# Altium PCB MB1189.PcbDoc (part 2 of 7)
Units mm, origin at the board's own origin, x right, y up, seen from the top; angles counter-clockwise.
Board outline 60.03 x 127.03 mm, 6 copper layers (TOP, L2_GND, L3_VCC, L4_SIG, L5_GND, BOTTOM), stack 1.58 mm thick; 273 components, 264 nets, 1114 pads, 811 vias.
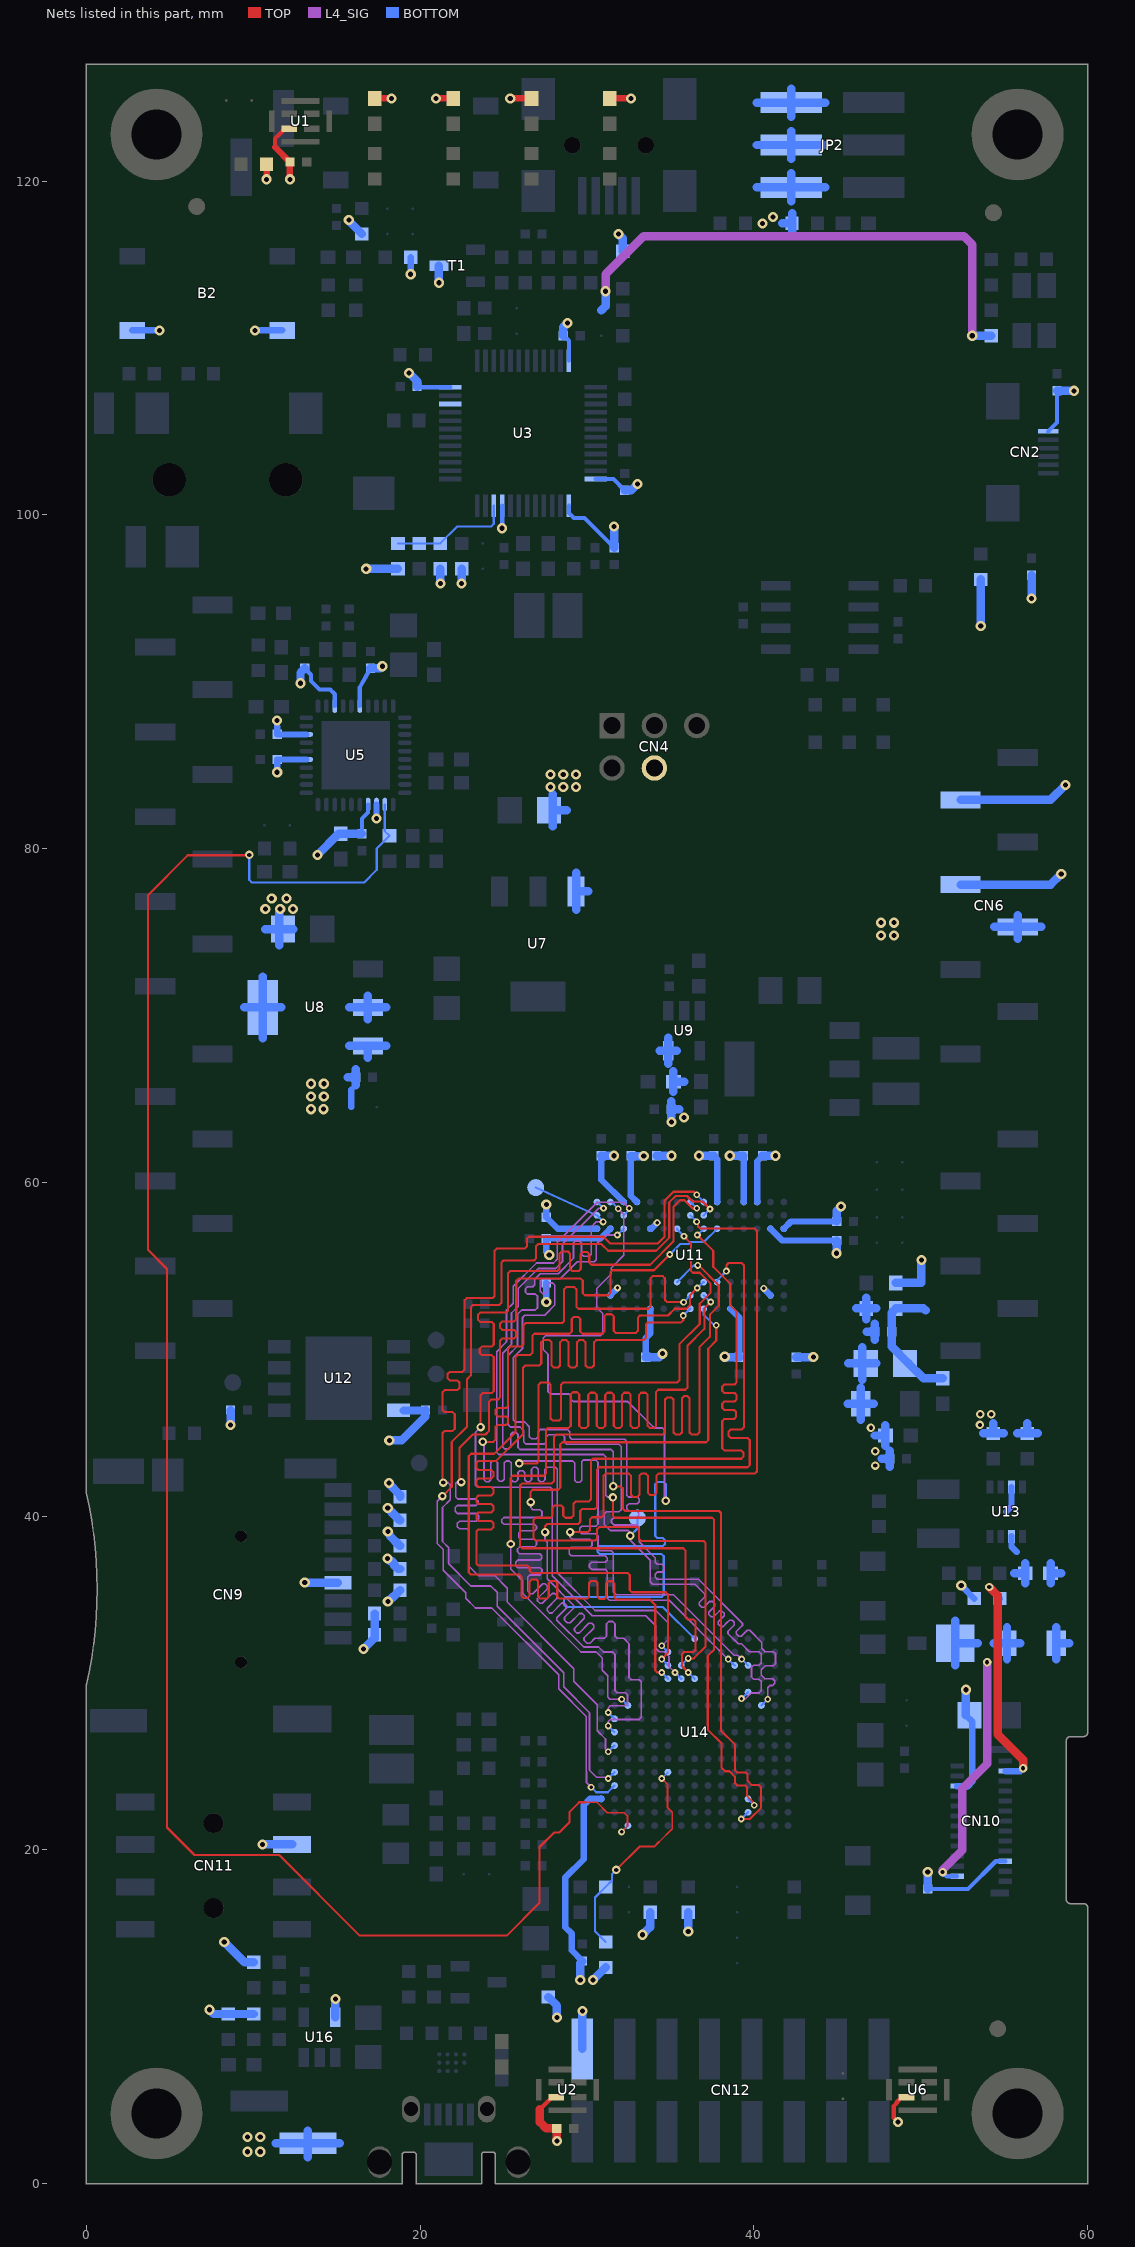
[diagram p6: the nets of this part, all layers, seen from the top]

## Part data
B1: library part "SW PUSHBUTTON", "Push-Button BLACK", Manuf_1="CHAU HUA"
B2: library part "SW PUSHBUTTON", "Push-Button BLUE", Manuf_1="CHAU HUA"
C1 C2 C41 C42 C43 C44 C45 C46 C47 C48 C49 C50 C51 C52 C55 C57 C58 C59 C62 C77 C78 C87: library part Cap, "Capacitor", Manuf_1=YAGEO, Manuf_Part_1=CC0402KRX7R7BB104
C3 C6 C16 C17 C23 C25 C30 C53 C54 C64 C67 C68 C69 C70 C71 C72 C73 C74 C75 C84 C88 C89 C90 C91 C92 C95 C97: library part CAP, "Capacitor", Manuf_1=YAGEO, Manuf_Part_1=CC0402KRX7R7BB104
C4: library part CAP, "Capacitor"
C5 C7 C8 C9 C12 C14 C34 C40: library part Capacitor_ST, "Capacitor 0402 / 0603 / 0805", Manuf_1=YAGEO, Manuf_Part_1=CC0402KRX7R7BB104
C10 C11: library part Capacitor_ST, "Capacitor 0402 / 0603 / 0805", Manuf_1=YAGEO, Manuf_Part_1=CC0603JRNPO9BN100
C13: library part Cap, "Capacitor"
C15 C29 C32 C35 C37 C56: library part Cap_TAJA106K016R, "Capacitor, Tantalum, 10uF, 16V, 10%, 3Ohms, pkg Type_A (3216 metric), T=1.6mm", Manuf_1=AVX, Manuf_Part_1=TAJA106K016R
C18 C19 C22 C31: library part CAP, "Capacitor", Manuf_1=YAGEO, Manuf_Part_1=CC0603KRX5R7BB105
C20 C21: library part Cap_22nF_X7R_10%_0603, "Capacitor,22nF,50V,X7R,10%,0603,YAGEO", Manuf_1=YAGEO, Manuf_Part_1=CC0603KRX7R9BB223
C24 C27: library part Cap_150pF_NPO_5%_0603, "Capacitor,150pF,50V,NPO,5%,0603,YAGEO", Manuf_1=YAGEO, Manuf_Part_1=CC0603JRNPO9BN151
C26: library part Cap_20pF_NPO_5%_0402, "Capacitor,20pF,50V,NPO,5%,0402,YAGEO", Manuf_1=YAGEO, Manuf_Part_1=CC0402JRNPO9BN200
C33 C38: library part "CAP SMD 0603  X5R 1µF 25V 10%", "Capacitor", Manuf_1=YAGEO, Manuf_Part_1=CC0603KRX5R7BB105, Rated voltage=25V, Temperature Max=+125°C, Temperature Min=-55°C, Tolerance=10%
C36: library part Cap_TAJB106K025RNJ, "Capacitor, Tantalum, 10uF, 25V, 10%, 2.5ohms, pkg Type_B (3528 metric), T=1.9mm", Manuf_1=AVX, Manuf_Part_1=TAJB106K025RNJ
C39: library part "CAP SMD 0603  X7R 10000PF 50V 10%", "0603  X7R 10NF", Manuf_1=YAGEO, Manuf_Part_1=CC0603KRX7R9BB103, Rated voltage=50V, Temperature Max=+125°C, Temperature Min=-55°C, Tolerance=10%
C60 C82 C98 C101: library part Cap_TAJA475K016R, "Capacitor, Tantalum, 4.7uF, 16V, 10%, 4ohms, pkg Type_A (3216 metric), T=1.6mm", Manuf_1=AVX, Manuf_Part_1=TAJA475K016R
C61: library part "Cap Pol1", "Polarized Capacitor (Radial)", Manuf_1=YAGEO, Manuf_Part_1=CC1206KKX7R8BB475
C63 C66: library part CAP, "Capacitor", Manuf_1=YAGEO, Manuf_Part_1=CC0603KRX7R9BB103
C65 C80 C86: library part Cap_TAJA105K016RNJ, "Capacitor, Tantalum, 1uF, 16V, 10%, 11Ohms, pkg Type_A (3216 metric), T=1.6mm", Manuf_1=AVX, Manuf_Part_1=TAJA105K016RNJ
C76 C81 C96: library part Cap, "Capacitor", Manuf_1=YAGEO, Manuf_Part_1=CC1206KKX7R7BB225
C79: library part CAP, "Capacitor", Manuf_1=YAGEO, Manuf_Part_1=CC1206KKX7R9BB475
C83 C85: library part CAP, "Capacitor", Manuf_1=YAGEO, Manuf_Part_1=CC0603CRNPO9BN8R2
C93 C94: library part CAP, "Capacitor", Manuf_1=YAGEO, Manuf_Part_1=CC0603CRNPO9BN3R0
CN1: library part "USB-MINI-typeB connector", "USB-MINI-typeB connector", Manuf_1=NELTRON, Manuf_Part_1=5075BMR-05-SM
CN2: "ZIF connector placed bottom side", Manuf_1=ATOM, Manuf_2=Hirose, Manuf_Part_1=FPC05006-09200
CN3: Manuf_1=QIAOD
CN4: library part "Header 3X2", "Header, 3-Pin, Dual row"
CN5: library part "Header 10X1_Female", "Header, 10-Pin, Single row,female", Manuf_1=SAMTEC, Manuf_Part_1=SSW-110-22-x-S-VS
CN6 CN7: library part "Header 8X1_Female", "Header, 8-Pin, Single row,female", Manuf_1=SAMTEC, Manuf_Part_1=SSW-108-22-x-S-VS
CN8: library part "Header 6X1_Female", "Header, 6-Pin, Single row,female SMD", Manuf_1=SAMTEC, Manuf_Part_1=SSW-106-22-x-S-VS
CN9: library part SMS016AFA5E, "MicroSD Card Conn, Reversed-Type, Mnt Push-Push, Positionning holes", Manuf_1=Yamaichi
CN10: "ZIF connector placed bottom side", Manuf_1=ATOM, Manuf_2=Hirose, Manuf_Part_1=FPC03025-14201
CN11: library part SSM-104-L-DH, "Header, 4-Pin, Dual row", Manuf_1=SAMTEC
CN12: library part "Header 8X2", "Header, 8-Pin, Dual row", Manuf_1=SAMTEC, Manuf_Part_1=TSM-108-01-x-DV
CN13: Manuf_1=MOLEX
D1 D2 D3 D4 U4: Manuf_1=ST
D5: "2-line IPAD, EMI filter including ESD protection", Manuf_1=ST
JP1 JP5: library part JP2, Manuf_1=SAMTEC, Manuf_Part_1=TSM-102-01-x-SV
JP2: library part "Header 3X2", "Header, 3-Pin, Dual row", Manuf_1=SAMTEC, Manuf_Part_1=TSM-103-01-x-DV
L1 L2 L3 L5: library part Inductor, "Inductor", Manuf_1="Tai-Tech Advanced Electronics", Manuf_Part_1=FCM1608KF-601T05
L4: library part Inductor, "Inductor", Manuf_1="Murata Manufacturing", Manuf_Part_1=LQH32PN4R7NN0L
LD1 LD7 LD8: library part LED2, "Typical RED, GREEN, YELLOW, AMBER GaAs LED", Manuf_1="Everlight Electronics", Manuf_Part_1=19-217/G7C-AN1P2/3T
LD2: library part LED2, "Typical RED, GREEN, YELLOW, AMBER GaAs LED", Manuf_1="Everlight Electronics", Manuf_Part_1=19-217/S2C-AM2N2VY/3T
LD3 LD5 LD9: library part LED2, "Typical RED, GREEN, YELLOW, AMBER GaAs LED", Manuf_1="Everlight Electronics", Manuf_Part_1=19-217/R6C-AL1M2VY/3T
LD4: library part LED2, "Typical RED, GREEN, YELLOW, AMBER GaAs LED", Manuf_1="Everlight Electronics", Manuf_Part_1=19-217/BHC-ZL1M2RY/3T
LD6: library part HSMF-A201-A00J1, Manuf_1=EVERLIGHT
R1: library part Res_0_5%_0402, "Resistor", Manuf_1=YAGEO, Manuf_Part_1=RC0603FR-0710KL
R2 R49: library part Res1, "Resistor", Manuf_1=YAGEO, Manuf_Part_1=RC0603FR-07510RL
R3 R4 R5 R158: library part Res1, "Resistor", Manuf_1=YAGEO, Manuf_Part_1=RC0603FR-07680RL
R6 R8: library part res1, "Resistor", Manuf_1=YAGEO, Manuf_Part_1=RC0603FR-07100KL
R7: library part res1, "Resistor", Manuf_1=YAGEO, Manuf_Part_1=RC0603FR-07820RL
R9 R122 R149 R152: library part Res1, "Resistor", Manuf_1=YAGEO, Manuf_Part_1=RC0402FR-0710KL
R10 R11 R17: library part Res1, "Resistor", Manuf_1=YAGEO, Manuf_Part_1=RC0603FR-07100RL
R12: library part Resistor_ST, "Resistor", Manuf_1=YAGEO, Manuf_Part_1=RC0603FR-071K5L
R13 R14: library part Resistor_ST, "Resistor", Manuf_1=YAGEO, Manuf_Part_1=RC0603JR-070RL
R15 R35: library part Resistor_ST, "Resistor 0402 / 0603 / 0805", Manuf_1=YAGEO, Manuf_Part_1=RC0603FR-07100RL
R16: library part Res1, "Resistor", Manuf_1=YAGEO, Manuf_Part_1=RC0603FR-0736KL
R18: library part Res1, "Resistor", Manuf_1=YAGEO, Manuf_Part_1=RC0603FR-07330RL
R19: library part res1, "Resistor", Manuf_1=YAGEO, Manuf_Part_1=RC0603FR-07220KL
R20: library part Resistor_ST, "Resistor", Manuf_1=YAGEO, Manuf_Part_1=RC0603FR-07100RL
R21 R23 R24 R41 R46 R57 R87 R117 R123 R131 R132 R133 R135 R151 R156 R159 R160 R161: library part Res1, "Resistor", Manuf_1=YAGEO, Manuf_Part_1=RC0603JR-070RL
R22: library part Res1, "Resistor", Manuf_1=YAGEO, Manuf_Part_1=RC0603FR-072K7L
R25 R36 R118: library part Res1, "Resistor", Manuf_1=YAGEO, Manuf_Part_1=RC0603FR-074K7L
R26 R27 R30: library part Resistor_ST, "Resistor 0402 / 0603 / 0805", Manuf_1=YAGEO, Manuf_Part_1=RC0603FR-07100KL
R28 R38: library part Resistor_ST, "Resistor", Manuf_1=YAGEO, Manuf_Part_1=RC0402FR-0710KL
R29 R31: library part Resistor_ST, "Resistor 0402 / 0603 / 0805"
R32 R33: library part Resistor_ST, "Resistor 0402 / 0603 / 0805", Manuf_1=YAGEO, Manuf_Part_1=RC0603FR-074K7L
R34: library part Res1, "Resistor", Manuf_1=YAGEO, Manuf_Part_1=RC0402FR-07100KL
R37: library part Resistor_ST, "Resistor 0402 / 0603 / 0805", Manuf_1=YAGEO, Manuf_Part_1=RC0603FR-072K7L
R39 R40: library part Res_51_1%_0402, "Resistor", Manuf_1=YAGEO, Manuf_Part_1=RC0402FR-0751RL
R42 R59: library part Res1, "Resistor", Manuf_1=YAGEO, Manuf_Part_1=RC0603FR-07100KL
R43 R119 R144: library part Res1, "Resistor"
R47 R48: library part Res1, "Resistor", Manuf_1=YAGEO, Manuf_Part_1=RC0603FR-0747KL
R55: library part Res_10K_1%_0402, "Resistor", Manuf_1=YAGEO, Manuf_Part_1=RC0402FR-0710KL
R58: library part Res1, "Resistor", Manuf_1=YAGEO, Manuf_Part_1=RC0603FR-0710RL
R86 R114 R115 R116 R120 R155 R157: library part res1, "Resistor", Manuf_1=YAGEO, Manuf_Part_1=RC0603FR-0747KL
R121 R124: library part Res1, "Resistor", Manuf_1=YAGEO, Manuf_Part_1=RC0603FR-072K2L
R140 R142: library part Res1, "Resistor", Manuf_1=YAGEO, Manuf_Part_1=RC0603FR-071K5L
R143: library part res1, "Resistor", Manuf_1=YAGEO, Manuf_Part_1=RC0603FR-07510RL
R150: library part res1, "Resistor"
R153: library part res1, "Resistor", Manuf_1=YAGEO, Manuf_Part_1=RC0603FR-07330RL
R154: library part res1, "Resistor", Manuf_1=YAGEO, Manuf_Part_1=RC0603FR-0710KL
SB1 SB2 SB3 SB4 SB5 SB6 SB7 SB8 SB9 SB10 SB11 SB12 SB13 SB14 SB15 SB16 SB17 SB18 SB19: library part "Circuit Breaker", "Circuit Breaker"
T1 T3: library part NPN, "NPN Bipolar Transistor", Manuf_Part_1=MMBT9013
U1 U2 U6: "MEMS audio sensor omnidirectional digital microphone for industrial applications", Manuf_1=ST
U3: library part STM32F10x(48pin), Manuf_1=ST, Manuf_Part_1=STM32F103CBT6
U5: "Low Power, Stereo DAC w/Headphone & Speaker Amps", Manuf_1=Cirrus, Manuf_Part_1=CS43L22-CNZ
U7: "LOW DROP FIXED AND ADJUSTABLE POSITIVE VOLTAGE REGULATORS (3.3 Volts)", Manuf_1=ST
U8 U10: library part LD1117, Manuf_1=ST
U9: "Ultra low drop-low noise BiCMOS voltage, regulators low ESR capacitors compatible", Manuf_1=ST
U11: library part IS42S32400F-6BL, "SDRAM 128MBit 166MHZ 90BGA", Manuf_1=ISSI
U12: library part MT25QL128ABA1EW9-0SIT, "128Mb, 3V, Multiple I/O Serial Flash Memory, Quad/Dual", Manuf_1=MICRON
U13: library part STLD40DPMR, Manuf_1=ST
U14: library part Manta_Dragon_TFBGA216, Manuf_1=ST, Manuf_Part_1="STM32F469NIH6U cut 1.0"
U16: library part STMPS2141STR, Manuf_1=ST
X1 X2: library part XTAL_8M_NX3225GD, "Crystal 8Mhz, 8pF, -+50PPM, SMD", Manuf_1=NDK, Manuf_Part_1="NX3225GD 8MHz EXS00A-CG04874", Manuf_Part_2=NX3225GD-8.000M-STD-CRA-3
X3: library part XTAL_32K_NX3215SA, "Crystal 32.768kHz, 6pF, -+20PPM, R=50K, SMD", Manuf_1=NDK, Manuf_Part_1="NX3215SA 32.768KHz EXS00A-MU00525"
Z1: library part "D Schottky", "Schottky Diode", Manuf_1=ST

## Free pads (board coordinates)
  round 0.508 on Mech16: 1(-26.171,-56.053) 1(115.945,-55.727)
  round 1.016 smd far side mask+1.016: ""(6.604,118.491) ""(54.356,118.11) ""(54.61,9.271)
  round 1.016 smd mask+1.016: ""(6.604,118.491) ""(54.356,118.11) ""(54.61,9.271)

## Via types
v1: diameter 0.61/0.61/0.61 (per signal layer), hole 0.305, TOP to BOTTOM, 321 vias
v2: diameter 0.508/0.508/0.508 (per signal layer), hole 0.254, TOP to BOTTOM, 247 vias
v3: diameter 0.406/0.406/0.406 (per signal layer), hole 0.203, TOP to BOTTOM, 243 vias

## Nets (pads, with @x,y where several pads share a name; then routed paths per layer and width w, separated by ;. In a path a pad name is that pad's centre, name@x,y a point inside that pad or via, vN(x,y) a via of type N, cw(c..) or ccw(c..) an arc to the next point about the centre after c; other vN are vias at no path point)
+1V8: C16.1 C17.1 C30.1 C31.1 C32.1 U5.13 U5.16 U5.34 U8.2 U8.4 | length 25.8
  BOTTOM w0.254: C17.1@13.081,90.805 13.462,90.424 13.462,90.043 13.97,89.535 14.605,89.535 14.879,89.261 U5.13@14.879,88.548 ; U5.16@16.379,88.548 16.379,89.658 C16.1@17.018,90.805 ; C30.1@16.51,80.899 16.51,81.8 16.879,82.169 U5.34@16.879,82.648
  BOTTOM w0.508: 9.46,70.485 U8.4@10.566,70.485 ; 10.566,68.63 U8.4@10.566,70.485 ; 10.566,72.34 U8.4@10.566,70.485 ; 10.718,75.184 C32.1@11.557,75.184 ; 11.557,74.218 C32.1@11.557,75.184 ; v1@11.557,76.15 C32.1@11.557,75.184 ; 11.671,70.485 U8.4@10.566,70.485 ; C32.1@12.396,75.184 C32.1@11.557,75.184 ; v1(12.827,89.916) 12.827,90.551 C17.1@13.081,90.805 ; v1(13.843,79.629) 15.113,80.899 C31.1@15.24,80.899 C30.1@16.51,80.899 ; 15.761,70.485 U8.2@16.866,70.485 ; 16.866,69.773 U8.2@16.866,70.485 ; 16.866,71.197 U8.2@16.866,70.485 ; C16.1@17.018,90.805 17.602,90.805 v1(17.729,90.932) ; 17.972,70.485 U8.2@16.866,70.485
  other v1: 10.719,76.378 11.608,76.378 12.37,76.378 11.1,77.013 11.989,77.013
+3V3: B2.1 B2.4 C1.2 C2.2 C6.2 C23.2 C25.1 C41.1 C42.1 C43.1 C44.1 C45.1 C46.1 C47.1 C48.1 C49.1 C50.1 C51.1 C52.1 C57.1 C58.1 C59.1 C62.1 C82.1 C97.2 CN2.1 CN6.2 CN6.4 CN9.4 CN10.6 CN10.21 CN11.5 CN12.1 JP5.1 LD1.1 LD2.1 LD3.1 LD4.1 R1.2 R6.1 R10.1 R33.1 R34.1 R36.1 R43.1 R55.2 R86.1 R114.1 R115.1 R116.1 R118.2 R120.1 R121.1 R124.1 R140.1 R142.1 R149.2 R150.2 R153.2 R157.1 R158.2 SB8.2 U1.1 U2.1 U5.5 U5.8 U5.33 U6.1 U8.3 U11.A7 U11.B2 U11.B7 U11.C9 U11.D9 U11.E1 U11.F9 U11.L1 U11.L7 U11.M9 U11.N9 U11.P2 U11.P7 U11.R7 U12.8 U14.C1 | length 166.9
  TOP w0.254: 11.303,122.047 11.303,122.554 11.554,122.805 ; 11.554,122.806 11.894,123.146 U1.1@12.152,123.146 ; 27.178,4.444 27.556,4.822 ; 27.556,4.823 27.896,5.163 U2.1@28.154,5.163 ; v1(48.641,3.683) 48.387,3.937 48.387,4.651 48.558,4.822 48.558,4.87 48.851,5.163 U6.1@49.156,5.163
  TOP w0.381: v1(10.795,120.117) R1.2@10.795,121.031 ; 11.303,122.047 C1.2@12.192,121.158 v1(12.192,120.117) ; LD1.1@17.272,124.968 v1(18.288,124.968) ; v1(20.955,124.968) LD2.1@21.971,124.968 ; v1(25.4,124.968) LD3.1@26.67,124.968 ; LD4.1@31.369,124.968 v1(32.639,124.968)
  TOP w0.508: 27.178,4.444 27.178,3.683 27.559,3.302 C2.2@28.194,3.302 v1(28.194,2.54)
  BOTTOM w0.254: C97.2@50.419,17.653 52.832,17.653 54.496,19.317 CN10.21@55.075,19.317 ; CN2.1@57.635,105.009 58.166,105.54 C6.2@58.166,107.442
  BOTTOM w0.381: B2.4@2.739,111.061 v1(4.381,111.061) ; v1(10.096,111.061) B2.1@11.739,111.061 ; v1(11.422,87.681) 11.422,87.325 11.43,87.317 C23.2@11.43,86.868 11.45,86.848 U5.8@13.179,86.848 ; v1(11.43,84.582) C25.1@11.43,85.344 11.815,85.348 U5.5@13.179,85.348 ; SB8.2@15.875,64.516 15.875,65.557 ; v1(17.379,81.808) U5.33@17.379,82.648 ; v1(19.431,114.427) R10.1@19.431,115.443 ; v1(27.559,52.832) C52.1@27.559,53.975 ; v1(27.559,58.674) C48.1@27.559,57.912 28.245,57.226 U11.R7@30.595,57.226 ; v1(27.737,55.651) 27.559,55.829 C50.1@27.559,56.642 30.811,56.642 U11.P7@31.395,57.226 ; R149.2@29.718,13.335 29.083,13.97 29.083,14.986 28.702,15.367 28.702,18.339 29.794,19.431 29.794,22.67 30.175,23.051 U14.C1@30.849,23.051 ; C47.1@30.861,61.595 30.861,60.16 U11.N9@32.195,58.826 ; U11.P2@31.395,53.226 31.828,53.659 v3(31.828,53.674) ; C46.1@32.639,61.595 32.618,61.574 32.618,59.203 U11.M9@32.995,58.826 ; C59.1@33.528,49.53 33.528,50.673 33.795,50.94 U11.L1@33.795,52.426 ; U11.L7@33.795,57.226 33.842,57.226 v3(34.198,57.582) ; C44.1@37.592,61.595 37.795,61.392 U11.F9@37.795,58.826 ; U11.E1@38.595,52.426 39.116,51.905 C58.1@39.116,49.53 ; C43.1@39.37,61.595 39.395,61.57 U11.D9@39.395,58.826 ; U11.C9@40.195,58.826 40.195,61.277 C42.1@40.513,61.595 ; v3(40.589,53.645) 40.995,53.239 U11.B2@40.995,53.226 ; U11.B7@40.995,57.226 41.706,56.515 C51.1@44.958,56.515 ; U11.A7@41.795,57.226 42.227,57.658 C49.1@44.958,57.658 ; CN10.6@52.175,23.817 52.832,23.817 53.086,24.071 53.086,27.686 C82.1@52.705,28.067 ; v1(52.426,35.839) R118.2@53.213,35.052
  BOTTOM w0.508: v1(7.366,10.414) 7.62,10.16 R158.2@8.509,10.16 R157.1@10.033,10.16 ; v1(8.255,14.478) 9.474,13.259 R43.1@10.033,13.259 ; v1(8.636,45.466) R55.2@8.636,46.355 ; v1(10.541,20.32) CN11.5@12.318,20.32 ; 11.353,2.413 JP5.1@13.271,2.413 ; v1(13.081,36.017) CN9.4@15.071,36.017 ; 13.271,1.574 JP5.1@13.271,2.413 ; 13.271,3.15 JP5.1@13.271,2.413 ; 15.189,2.413 JP5.1@13.271,2.413 ; 15.646,66.294 C41.1@16.129,66.294 ; v1(15.723,117.678) 15.723,117.627 R6.1@16.51,116.84 ; 15.761,68.185 U8.3@16.866,68.185 ; 16.129,65.811 C41.1@16.129,66.294 ; 16.129,66.777 C41.1@16.129,66.294 ; v1(16.612,32.029) 17.272,32.69 R124.1@17.272,32.893 R121.1@17.272,34.163 ; v1(16.764,96.774) R33.1@18.669,96.774 ; 16.866,67.473 U8.3@16.866,68.185 ; 17.972,68.185 U8.3@16.866,68.185 ; v1(18.034,37.465) 18.161,37.338 18.266,37.338 18.415,37.189 18.415,37.084 18.669,36.83 R116.1@18.796,36.83 ; v1(18.057,40.482) 18.266,40.273 18.266,40.259 18.774,39.751 R114.1@18.796,39.751 ; v1(18.059,34.874) 18.089,34.874 18.415,35.201 18.437,35.201 R120.1@18.796,35.56 ; v1(18.058,39.083) 18.161,38.981 18.161,38.84 18.774,38.227 R115.1@18.796,38.227 ; v1(18.136,41.986) 18.136,41.935 18.796,41.275 R86.1@18.796,41.148 ; v1(18.148,44.536) 18.882,44.536 20.294,45.948 C62.1@20.294,46.329 ; U12.8@19.013,46.329 C62.1@20.294,46.329 ; C62.1@20.32,46.355 C62.1@20.294,46.329 ; R153.2@27.686,11.176 28.194,10.668 v1(28.194,9.957) ; v1(29.591,12.192) 29.591,13.208 R149.2@29.718,13.335 ; CN12.1@29.718,8.063 v1(29.718,10.338) ; v1(30.353,12.192) R150.2@31.115,12.954 ; C47.1@30.861,61.595 v1(31.623,61.595) ; C46.1@32.618,61.574 v1(33.401,61.574) ; v1(33.325,14.91) 33.782,15.367 R142.1@33.782,16.256 ; C59.1@33.528,49.53 34.315,49.53 v1(34.519,49.733) ; C45.1@34.163,61.595 v1(35.052,61.595) ; v1(36.068,15.113) R140.1@36.068,16.256 ; v1(36.703,61.595) C44.1@37.592,61.595 ; v1(38.252,49.555) 38.278,49.53 C58.1@39.116,49.53 ; v1(38.557,61.595) C43.1@39.37,61.595 ; C42.1@40.513,61.595 v1(41.3,61.595) ; C57.1@42.545,49.53 v1(43.561,49.53) ; v1(44.958,55.753) C51.1@44.958,56.515 ; C49.1@44.958,57.658 44.958,58.293 v1(45.212,58.547) ; C97.2@50.419,17.653 v1(50.419,18.669) ; CN6.4@52.387,77.851 57.785,77.851 v1(58.42,78.486) ; CN6.2@52.387,82.931 57.785,82.931 v1(58.674,83.82) ; C82.1@52.705,28.067 v1(52.705,29.591) ; v1(53.594,93.345) R36.1@53.594,96.139 ; v1(56.642,94.996) R34.1@56.642,96.393 ; C6.2@58.166,107.442 v1(59.182,107.442)
  other v1: 9.652,1.905 10.414,1.905 9.652,2.794 10.414,2.794 13.462,64.389 14.199,64.389 13.462,65.151 14.224,65.151 13.462,65.913 14.224,65.913
+3V3_ST_LINK: C5.2 C7.2 C8.2 C9.2 C38.1 C40.2 CN4.4 R21.2 R30.2 R31.1 SB16.1 T1.3 U3.1 U3.9 U3.24 U3.36 U3.48 U9.5 | length 55.8
  L4_SIG w0.508: v1(31.115,113.411) 31.115,114.427 33.401,116.713 52.578,116.713 53.086,116.205 v1(53.086,110.744)
  BOTTOM w0.254: C7.2@19.812,107.696 19.856,107.652 U3.24@21.812,107.652 ; v1(24.912,99.207) U3.9@24.912,100.552 ; C5.2@28.575,110.744 28.912,110.446 U3.36@28.912,109.252 ; U3.1@28.912,100.552 28.912,100.12 29.21,99.822 29.845,99.822 C9.2@31.623,98.044 ; U3.48@30.512,102.152 31.579,102.152 C8.2@32.258,101.473
  BOTTOM w0.508: v1(19.329,108.509) 19.812,108.026 C7.2@19.812,107.696 ; v1(21.125,113.919) T1.3@21.125,114.935 ; v1(21.209,95.885) R31.1@21.209,96.774 ; v1(22.479,95.885) R30.2@22.479,96.774 ; C5.2@28.575,110.744 28.575,111.252 v1(28.829,111.506) ; SB16.1@30.861,112.268 31.115,112.522 v1(31.115,113.411) ; C9.2@31.623,98.044 v1(31.623,99.314) ; C8.2@32.258,101.473 32.639,101.473 v1(33.02,101.854) ; 34.343,67.888 U9.5@34.864,67.888 ; 34.864,67.113 U9.5@34.864,67.888 ; 34.864,68.663 U9.5@34.864,67.888 ; v1@35.052,63.906 C40.2@35.052,64.389 ; 35.052,64.872 C40.2@35.052,64.389 ; 35.179,65.43 C38.1@35.179,66.04 ; 35.179,66.65 C38.1@35.179,66.04 ; 35.385,67.888 U9.5@34.864,67.888 ; 35.535,64.389 C40.2@35.052,64.389 ; 35.827,66.04 C38.1@35.179,66.04 ; v1(53.086,110.744) R21.2@54.229,110.744
  other v1: 35.052,63.627 35.814,63.881
+5V: C29.1 CN6.5 D1.1 JP2.2 JP2.4 JP2.6 L1.1 R7.2 SB13.1 U7.3 U16.5 | length 34.2
  BOTTOM w0.508: U16.5@14.92,9.963 v1(14.92,11.049) ; 27.94,81.33 C29.1@27.94,82.296 ; 27.94,83.262 C29.1@27.94,82.296 ; 28.779,82.296 C29.1@27.94,82.296 ; 29.351,76.34 U7.3@29.351,77.445 ; 29.351,78.551 U7.3@29.351,77.445 ; 30.063,77.445 U7.3@29.351,77.445 ; v1(31.877,116.84) 32.131,116.586 D1.1@32.131,115.806 ; 40.184,119.634 JP2.6@42.229,119.634 ; 40.184,122.174 JP2.4@42.229,122.174 ; 40.184,124.714 JP2.2@42.229,124.714 ; 41.694,117.475 R7.2@42.291,117.475 ; 42.229,118.795 JP2.6@42.229,119.634 ; 42.229,120.473 JP2.6@42.229,119.634 ; 42.229,121.335 JP2.4@42.229,122.174 ; 42.229,123.013 JP2.4@42.229,122.174 ; 42.229,123.875 JP2.2@42.229,124.714 ; 42.229,125.553 JP2.2@42.229,124.714 ; 42.291,116.865 R7.2@42.291,117.475 ; 42.291,118.085 R7.2@42.291,117.475 ; 44.274,119.634 JP2.6@42.229,119.634 ; 44.274,122.174 JP2.4@42.229,122.174 ; 44.274,124.714 JP2.2@42.229,124.714 ; L1.1@48.514,53.975 SB13.1@50.038,53.975 v1(50.038,55.347) ; 54.406,75.311 CN6.5@55.816,75.311 ; 55.816,74.599 CN6.5@55.816,75.311 ; 55.816,76.023 CN6.5@55.816,75.311 ; 57.227,75.311 CN6.5@55.816,75.311
  other v1: 47.625,74.803 48.387,74.803 47.625,75.565 48.387,75.565 27.813,83.693 28.575,83.693 29.337,83.693 27.813,84.455 28.575,84.455 29.337,84.455 40.513,117.475 41.148,117.856
A: C66.2 C79.1 CN10.24 U13.6 Z1.2 | length 25.1
  L4_SIG w0.508: v2(51.308,18.669) 51.308,18.796 52.476,19.964 52.476,23.647 53.975,25.146 v2(53.975,31.242)
  BOTTOM w0.254: v2(51.308,18.669) 51.56,18.417 CN10.24@52.175,18.417
  BOTTOM w0.381: U13.6@55.443,38.784 55.443,38.156 55.753,37.846
  BOTTOM w0.508: 52.07,31.051 Z1.2@52.07,32.385 ; 52.07,33.719 Z1.2@52.07,32.385 ; 53.417,32.385 Z1.2@52.07,32.385 ; 54.381,32.385 C79.1@55.169,32.385 ; 55.169,31.419 C79.1@55.169,32.385 ; 55.169,33.351 C79.1@55.169,32.385 ; 55.613,36.576 C66.2@56.261,36.576 ; 55.957,32.385 C79.1@55.169,32.385 ; 56.261,35.966 C66.2@56.261,36.576 ; 56.261,37.186 C66.2@56.261,36.576
A0: U11.G8 U14.D2 | length 57.1
  TOP w0.127: v2(21.336,41.199) 21.895,41.758 21.895,44.45 22.809,45.364 22.809,48.209 23.038,48.438 23.038,52.527 23.165,52.654 24.74,52.654 24.867,52.781 24.867,55.194 24.994,55.321 26.822,55.321 26.949,55.448 26.949,56.185 27.076,56.312 30.861,56.312 31.267,55.905 34.138,55.905 34.925,56.693 34.925,58.801 35.306,59.182 35.992,59.182 36.322,58.852 36.924,58.852 v3(37.372,58.403)
  L4_SIG w0.102: v2(21.336,41.199) 21.031,40.894 21.031,38.354 21.387,37.998 21.387,36.754 22.733,35.408 22.733,35.077 23.317,34.493 24.284,34.493 28.296,30.482 28.296,29.643 29.947,27.992 29.947,24.68 29.972,24.655 29.972,24.019 v3(30.242,23.749)
  BOTTOM w0.127: v3(30.242,23.749) 30.543,23.449 31.246,23.449 U14.D2@31.649,23.851 ; U11.G8@36.995,58.026 v3(37.372,58.403)
A1: U11.G9 U14.E2 | length 59.1
  TOP w0.127: v2(21.387,42.012) 21.387,42.037 21.336,42.088 21.336,44.983 21.463,45.11 21.946,45.11 22.073,45.237 22.073,46.101 21.946,46.228 21.463,46.228 21.336,46.355 21.336,47.422 21.463,47.549 22.225,47.549 22.352,47.676 22.352,48.006 22.225,48.133 21.768,48.133 21.641,48.26 21.641,48.514 21.768,48.641 22.53,48.641 22.657,48.768 22.657,52.934 22.784,53.061 24.333,53.061 24.46,53.188 24.46,55.905 24.587,56.032 26.264,56.032 26.391,56.159 26.391,56.617 26.518,56.744 30.988,56.744 31.394,56.337 34.239,56.337 34.646,56.744 34.646,58.903 35.179,59.436 36.398,59.436 v3(36.576,59.258)
  L4_SIG w0.102: v2(21.387,42.012) 21.666,42.012 21.793,41.885 21.793,40.97 21.336,40.513 21.336,38.48 21.717,38.099 21.717,37.135 23.038,35.814 24.232,35.814 24.613,35.433 24.613,34.596 28.6,30.608 28.6,29.769 30.15,28.22 30.15,24.764 30.569,24.346 31.2,24.346 v3(31.272,24.274)
  BOTTOM w0.127: v3(31.272,24.274) U14.E2@31.649,24.651 ; v3(36.576,59.258) 36.995,58.839 U11.G9@36.995,58.826
A2: U11.F7 U14.G2 | length 57.9
  TOP w0.127: v2(22.454,42.037) 22.352,42.139 22.352,44.094 23.152,44.895 23.91,44.895 24.13,45.114 24.13,46.863 24.257,46.99 24.663,46.99 24.79,47.117 24.79,50.526 24.917,50.653 25.629,50.653 25.756,50.78 25.756,51.034 25.629,51.161 24.917,51.161 24.79,51.288 24.79,51.542 24.917,51.669 25.629,51.669 25.756,51.796 25.756,54.102 25.883,54.229 29.616,54.229 29.743,54.102 29.743,53.365 29.87,53.238 31.267,53.238 31.394,53.365 31.394,54.61 31.521,54.737 34.011,54.737 v3(34.95,55.677)
  L4_SIG w0.102: v2(22.454,42.037) 22.2,42.037 22.123,41.961 22.123,41.148 22.25,41.021 23.343,41.021 23.47,40.894 23.47,40.767 23.343,40.64 22.225,40.64 22.098,40.513 22.098,40.284 22.225,40.157 23.368,40.157 23.495,40.03 23.495,39.827 23.368,39.7 22.352,39.7 22.225,39.573 22.225,39.37 22.352,39.243 22.809,39.243 22.936,39.116 22.936,36.982 23.495,36.424 24.232,36.424 ; 24.232,36.424 24.484,36.424 25.222,35.686 25.222,34.849 29.21,30.861 29.21,30.093 29.433,29.87 29.439,29.87 30.607,28.702 30.607,27.144 31.11,26.641 31.11,26.035 v3(31.272,25.874)
  BOTTOM w0.127: v3(31.272,25.874) U14.G2@31.649,26.251 ; v3(34.95,55.677) 35.585,56.312 36.093,56.312 36.22,56.439 37.008,56.439 U11.F7@37.795,57.226
A3: U11.F3 U14.H2 | length 56.3
  TOP w0.127: v2(27.483,39.04) 27.483,39.395 27.61,39.522 29.464,39.522 29.591,39.649 29.591,40.31 29.718,40.437 30.48,40.437 30.607,40.564 30.607,42.799 30.734,42.926 39.624,42.926 39.751,43.053 39.751,44.554 39.624,44.681 38.608,44.681 38.481,44.808 38.481,45.062 38.608,45.189 39.268,45.189 39.395,45.316 39.395,55.042 39.268,55.169 38.481,55.169 38.354,55.042 v3(38.354,54.686)
  L4_SIG w0.102: v2(27.483,39.04) 27.483,38.557 27.61,38.43 27.61,36.246 29.21,34.646 29.21,34.493 28.652,33.935 28.652,33.756 28.808,33.6 28.988,33.6 29.55,34.162 29.719,34.162 29.838,34.043 29.838,33.875 29.245,33.282 29.245,33.138 29.388,32.994 29.532,32.994 30.112,33.574 30.281,33.574 30.4,33.456 30.4,33.287 29.82,32.707 29.82,32.563 29.997,32.385 30.175,32.385 30.463,32.673 31.039,32.673 31.166,32.8 31.166,33.553 31.293,33.68 31.547,33.68 31.674,33.553 31.674,32.8 31.801,32.673 32.199,32.673 32.516,32.355 32.516,30.328 32.643,30.201 33.122,30.201 33.249,30.074 33.249,27.94 33.122,27.813 31.399,27.813 31.272,27.686 v3(31.272,27.428)
  BOTTOM w0.127: v3(31.272,27.428) U14.H2@31.649,27.051 ; U11.F3@37.795,54.026 37.795,54.127 v3(38.354,54.686)
A4: U11.G1 U14.J2 | length 58.3
  TOP w0.127: v2(26.619,40.843) 26.619,41.453 26.746,41.58 28.27,41.58 28.397,41.707 28.397,44.298 28.524,44.425 37.135,44.425 37.262,44.552 37.262,50.038 37.744,50.521 v3(37.744,51.435)
  L4_SIG w0.102: v2(26.619,40.843) 26.619,40.513 26.746,40.386 27.178,40.386 27.305,40.259 27.305,40.047 27.178,39.92 25.019,39.92 24.892,39.793 24.892,39.641 25.019,39.514 26.848,39.514 26.975,39.387 26.975,39.243 26.848,39.116 26.035,39.116 25.908,38.989 25.908,38.735 26.035,38.608 26.848,38.608 26.975,38.481 26.975,38.278 26.848,38.151 25.951,38.151 25.832,38.032 25.832,37.864 25.951,37.744 27.168,37.744 27.28,37.633 27.28,37.475 27.168,37.363 25.857,37.363 25.73,37.236 25.73,37.033 25.857,36.906 27.179,36.906 27.305,36.78 27.305,36.601 27.179,36.474 26.568,36.474 26.441,36.347 26.441,35.509 26.603,35.347 26.747,35.347 27.34,35.94 27.484,35.94 27.628,35.796 27.628,35.652 27.035,35.06 27.035,34.916 27.179,34.772 27.322,34.772 27.915,35.365 28.059,35.365 28.203,35.221 28.203,35.077 27.61,34.485 27.61,34.341 27.754,34.197 27.897,34.197 28.49,34.79 28.634,34.79 28.778,34.646 28.778,34.502 28.185,33.91 28.185,33.766 29.794,32.156 30.683,32.156 30.988,31.852 31.547,31.852 31.674,31.725 31.674,29.54 31.801,29.413 32.3,29.413 32.427,29.286 32.427,28.753 32.3,28.626 31.399,28.626 31.272,28.499 v3(31.272,28.228)
  BOTTOM w0.127: v3(31.272,28.228) U14.J2@31.649,27.851 ; U11.G1@36.995,52.426 36.995,52.057 37.617,51.435 v3(37.744,51.435)
A5: U11.G2 U14.K3 | length 59
  TOP w0.127: v2(25.425,38.329) 25.425,42.291 25.552,42.418 27.407,42.418 27.534,42.545 27.534,45.161 27.661,45.288 28.897,45.288 29.024,45.415 29.024,47.295 29.151,47.422 29.405,47.422 29.532,47.295 29.532,45.415 29.659,45.288 29.947,45.288 30.074,45.415 30.074,47.269 30.201,47.396 30.455,47.396 30.582,47.269 30.582,45.415 30.709,45.288 30.963,45.288 31.09,45.415 31.09,47.269 31.217,47.396 31.471,47.396 31.598,47.269 31.598,45.415 31.725,45.288 31.979,45.288 32.106,45.415 32.106,47.269 32.233,47.396 32.487,47.396 32.614,47.269 32.614,45.415 32.741,45.288 32.995,45.288 33.122,45.415 33.122,47.269 33.249,47.396 33.503,47.396 33.63,47.269 33.63,45.415 33.757,45.288 34.011,45.288 34.138,45.415 34.138,47.447 34.265,47.574 35.89,47.574 36.017,47.701 36.017,50.216 37.033,51.232 37.033,52.451 v3(37.414,52.832)
  L4_SIG w0.102: v2(25.425,38.329) 25.425,36.83 26.137,36.119 26.137,35.357 29.642,31.852 30.556,31.852 30.916,31.492 30.916,30.755 31.242,30.429 31.242,29.155 31.369,29.028 v3(32.072,29.028)
  BOTTOM w0.127: v3(32.072,29.028) U14.K3@32.449,28.651 ; U11.G2@36.995,53.226 37.389,52.832 v3(37.414,52.832)
A6: U11.G3 U14.M6 | length 58.2
  TOP w0.127: v3(34.472,30.628) 34.214,30.628 34.087,30.755 34.087,34.671 33.757,35.001 31.762,35.001 31.635,35.128 31.635,35.966 31.508,36.093 31.271,36.093 31.144,35.966 31.144,35.154 31.017,35.027 30.763,35.027 30.636,35.154 30.636,35.992 30.509,36.119 30.255,36.119 30.128,35.992 30.128,35.179 30.001,35.052 28.342,35.052 28.215,35.179 28.215,35.992 28.088,36.119 27.834,36.119 27.707,35.992 27.707,35.179 27.58,35.052 27.193,35.052 27.066,35.179 27.066,36.081 26.939,36.208 26.685,36.208 26.558,36.081 26.558,35.23 26.431,35.103 26.187,35.103 26.06,35.23 26.06,36.373 25.933,36.5 23.038,36.5 22.911,36.627 22.911,43.586 23.063,43.739 24.435,43.739 25.705,45.009 25.705,49.53 25.832,49.657 26.594,49.657 26.721,49.784 26.721,50.8 26.848,50.927 28.956,50.927 29.083,51.054 29.083,51.816 29.21,51.943 29.464,51.943 29.591,51.816 29.591,51.054 29.718,50.927 30.912,50.927 31.039,51.054 31.039,51.968 31.166,52.095 31.471,52.095 31.598,51.968 31.598,51.105 31.725,50.978 32.918,50.978 33.045,51.105 33.045,51.892 33.172,52.019 34.849,52.019 35.255,52.426 35.97,52.426 36.173,52.629 36.173,53.242 v3(36.599,53.668)
  BOTTOM w0.127: v3(34.472,30.628) U14.M6@34.849,30.251 ; v3(36.599,53.668) 36.957,54.026 U11.G3@36.995,54.026
A7: U11.H1 U14.N6 | length 59.8
  TOP w0.127: v3(34.472,31.428) 34.849,31.805 34.849,35.306 34.722,35.433 32.69,35.433 32.563,35.56 32.563,36.462 32.436,36.589 26.695,36.589 26.568,36.716 26.568,36.906 26.441,37.033 23.495,37.033 23.368,37.16 23.368,39.077 23.495,39.204 24.257,39.204 24.384,39.331 24.384,39.585 24.257,39.712 23.495,39.712 23.368,39.839 23.368,40.093 23.495,40.22 24.257,40.22 24.384,40.347 24.384,40.601 24.257,40.728 23.495,40.728 23.368,40.855 23.368,41.109 23.495,41.236 24.257,41.236 24.384,41.363 24.384,41.617 24.257,41.744 23.495,41.744 23.368,41.871 23.368,42.125 23.495,42.252 24.257,42.252 24.384,42.379 24.384,42.633 24.257,42.76 23.495,42.76 23.368,42.887 23.368,43.18 23.495,43.307 24.562,43.307 26.162,44.907 26.162,48.895 26.289,49.022 27.127,49.022 27.254,49.149 27.254,50.419 27.381,50.546 27.748,50.546 27.875,50.419 27.875,49.022 28.002,48.895 28.256,48.895 28.383,49.022 28.383,50.419 28.51,50.546 28.764,50.546 28.891,50.419 28.891,49.022 29.018,48.895 29.272,48.895 29.399,49.022 29.399,50.419 29.526,50.546 29.78,50.546 29.907,50.419 29.907,49.022 30.034,48.895 30.288,48.895 30.415,49.022 30.415,50.419 30.542,50.546 33.401,50.546 33.528,50.673 33.528,51.486 33.655,51.613 35.636,51.613 35.763,51.74 v3(35.763,52.019)
  BOTTOM w0.127: v3(34.472,31.428) U14.N6@34.849,31.051 ; v3(35.763,52.019) 36.17,52.426 U11.H1@36.195,52.426
A8: U11.H2 U14.P6 | length 57.4
  TOP w0.127: v2(23.749,44.45) 24.384,44.45 24.511,44.577 24.511,45.339 24.638,45.466 25.146,45.466 25.273,45.593 25.273,45.847 25.146,45.974 24.638,45.974 24.511,46.101 24.511,46.355 24.638,46.482 25.146,46.482 25.273,46.609 25.273,50.038 25.4,50.165 26.06,50.165 26.187,50.292 26.187,51.435 26.314,51.562 28.499,51.562 28.626,51.689 28.626,53.594 28.753,53.721 29.235,53.721 29.362,53.594 29.362,52.553 29.489,52.426 33.677,52.426 33.804,52.553 33.804,54.254 33.931,54.381 34.544,54.381 34.671,54.254 34.671,52.95 34.798,52.823 v3(35.789,52.823)
  L4_SIG w0.102: v2(23.749,44.45) 23.825,44.374 23.825,42.182 23.944,42.062 24.112,42.062 24.232,42.182 24.232,43.188 24.351,43.307 24.519,43.307 24.638,43.188 24.638,42.207 24.757,42.088 24.925,42.088 25.044,42.207 25.044,43.188 25.164,43.307 25.332,43.307 25.451,43.188 25.451,42.182 25.57,42.062 25.738,42.062 25.857,42.182 25.857,42.604 25.976,42.723 26.144,42.723 26.264,42.604 26.264,42.182 26.383,42.062 26.551,42.062 26.67,42.182 26.67,42.807 26.789,42.926 26.957,42.926 27.076,42.807 27.076,42.182 27.196,42.062 27.364,42.062 27.483,42.182 27.483,42.799 27.61,42.926 28.092,42.926 28.219,42.799 28.219,36.601 30.48,34.341 34.112,34.341 34.849,33.604 34.849,32.605 v3(34.472,32.228)
  BOTTOM w0.127: v3(34.472,32.228) U14.P6@34.849,31.851 ; v3(35.789,52.823) 36.191,53.226 U11.H2@36.195,53.226
A9: U11.J3 U14.M8 | length 57.6
  TOP w0.127: v3(36.072,30.628) 35.687,31.013 35.687,31.725 35.814,31.852 36.373,31.852 36.5,31.979 36.5,33.68 36.373,33.807 36.017,33.807 35.89,33.934 35.89,37.948 35.763,38.075 26.111,38.075 25.984,38.202 25.984,41.834 26.111,41.961 27.889,41.961 28.016,42.088 28.016,44.755 28.143,44.882 34.544,44.882 34.671,45.009 34.671,46.99 34.798,47.117 35.052,47.117 35.179,46.99 35.179,45.009 35.306,44.882 35.56,44.882 35.687,45.009 35.687,47.066 35.814,47.193 36.017,47.193 36.144,47.066 36.144,45.009 36.271,44.882 36.601,44.882 36.728,45.009 36.728,50.114 37.363,50.749 37.363,51.13
  TOP w0.13: v3(36.641,55.028) 36.692,55.028 37.897,53.823 37.897,52.603 37.363,52.07 37.363,51.13
  BOTTOM w0.127: U11.J3@35.395,54.026 36.396,55.028 v3(36.641,55.028) ; v3(36.072,30.628) U14.M8@36.449,30.251
A10: U11.G7 U14.N7 | length 57.5
  TOP w0.127: v3(36.068,31.471) 36.398,31.471 37.109,32.182 37.109,38.379 36.982,38.506 33.249,38.506 33.122,38.633 33.122,39.218 32.995,39.345 30.734,39.345 30.607,39.218 30.607,38.659 30.48,38.532 26.924,38.532 26.797,38.659 26.797,39.776 26.924,39.903 27.813,39.903 27.94,40.03 27.94,40.513 28.067,40.64 28.448,40.64 28.575,40.513 28.575,40.03 28.702,39.903 29.058,39.903 29.185,40.03 29.185,40.742 29.312,40.869 30.099,40.869 30.226,40.996 30.226,43.307 30.353,43.434 39.243,43.434 39.37,43.561 39.37,43.815 39.243,43.942 38.227,43.942 38.1,44.069 38.1,45.695 38.227,45.822 38.811,45.822 38.938,45.949 38.938,46.235 38.811,46.362 38.227,46.362 38.1,46.489 38.1,46.743 38.227,46.87 38.837,46.87 38.964,46.997 38.964,47.251 38.837,47.378 38.227,47.378 38.1,47.505 38.1,47.759 38.227,47.886 38.837,47.886 38.964,48.013 38.964,52.253 38.583,52.634 38.583,53.924 37.567,54.94 37.567,55.893 v3(36.614,56.845)
  BOTTOM w0.127: U14.N7@35.649,31.051 v3(36.068,31.471) ; v3(36.614,56.845) U11.G7@36.995,57.226
A11: U11.H9 U14.M7 | length 57.2
  TOP w0.127: v2(23.622,45.339) 23.622,47.244 23.749,47.371 24.282,47.371 24.409,47.498 24.409,49.524 24.282,49.651 23.698,49.651 23.571,49.778 23.571,50.032 23.698,50.159 24.282,50.159 24.409,50.286 24.409,51.511 24.282,51.638 23.597,51.638 23.47,51.765 23.47,52.07 23.597,52.197 25.146,52.197 25.273,52.324 25.273,54.559 25.4,54.686 28.219,54.686 28.346,54.813 28.346,55.728 28.473,55.855 28.854,55.855 28.981,55.728 28.981,54.813 29.108,54.686 29.495,54.686 29.622,54.813 29.622,55.702 29.749,55.829 30.003,55.829 30.13,55.702 30.13,55.194 30.257,55.067 33.782,55.067 35.179,56.464 35.179,58.547 35.56,58.928 35.839,58.928 36.323,58.445 v3(36.576,58.445)
  L4_SIG w0.102: v2(23.622,45.339) 23.317,45.034 23.317,41.859 23.444,41.732 27.788,41.732 27.915,41.605 27.915,36.424 30.315,34.023 33.515,34.023 34.116,33.422 34.116,32.081 34.325,31.873 34.625,31.873 34.916,31.581 34.916,30.984 v3(35.272,30.628)
  BOTTOM w0.127: v3(35.272,30.628) U14.M7@35.649,30.251 ; U11.H9@36.195,58.826 v3(36.576,58.445)
A14: U11.J7 U14.N12 | length 57.1
  TOP w0.127: v2(25.933,43.155) 26.975,43.155 27.102,43.282 27.102,47.879 27.229,48.006 27.686,48.006 27.813,47.879 27.813,45.847 27.94,45.72 28.321,45.72 28.448,45.847 28.448,47.879 28.575,48.006 35.408,48.006 35.535,48.133 35.535,50.292 36.754,51.511 36.754,52.73 37.389,53.365 37.389,53.95 36.754,54.585 36.347,54.585 36.22,54.712 36.22,56.363 v3(35.814,56.769)
  L4_SIG w0.102: v2(25.933,43.155) 25.933,43.18 26.06,43.307 29.144,43.307 29.271,43.18 29.271,42.139 29.372,42.037 29.576,42.037 29.677,42.139 29.677,43.256 29.779,43.358 30.531,43.358 30.658,43.231 30.658,39.522 30.531,39.395 29.693,39.395 29.566,39.268 29.566,39.065 29.693,38.938 30.531,38.938 30.658,38.811 30.658,38.049 30.785,37.922 31.445,37.922 31.572,37.795 31.572,35.458 31.75,35.281 35.179,35.281 38.807,31.652 39.04,31.652 v3(39.264,31.428)
  BOTTOM w0.127: U11.J7@35.395,57.226 35.395,57.188 v3(35.814,56.769) ; v3(39.264,31.428) 39.641,31.051 U14.N12@39.649,31.051
A15: U11.H8 U14.N11 | length 57.8
  TOP w0.127: v2(28.981,39.04) 30.048,39.04 30.175,39.167 30.175,39.802 30.302,39.929 30.861,39.929 30.988,40.056 30.988,42.418 31.115,42.545 32.503,42.545 32.63,42.418 32.63,41.275 32.757,41.148 33.011,41.148 33.138,41.275 33.138,42.418 33.265,42.545 33.519,42.545 33.646,42.418 33.646,41.402 33.773,41.275 34.027,41.275 34.154,41.402 34.154,42.418 34.281,42.545 40.056,42.545 40.183,42.672 40.183,57.099 40.056,57.226 36.779,57.226 36.652,57.353 36.652,57.556 v3(36.566,57.642)
  L4_SIG w0.102: v2(28.981,39.04) 28.981,38.735 29.108,38.608 30.175,38.608 30.302,38.481 30.302,38.252 30.175,38.125 29.058,38.125 28.931,37.998 28.931,37.744 29.058,37.617 31.09,37.617 31.217,37.49 31.217,37.363 31.09,37.236 30.276,37.236 30.15,37.11 30.15,36.931 30.276,36.805 31.09,36.805 31.217,36.678 31.217,35.077 31.344,34.95 34.925,34.95 38.447,31.428 v3(38.464,31.428)
  BOTTOM w0.127: U11.H8@36.195,58.026 36.566,57.655 v3(36.566,57.642) ; v3(38.464,31.428) 38.841,31.051 U14.N11@38.849,31.051
AIN_1: R31.2 R32.2 R33.2 U3.10 | length 7.3
  BOTTOM w0.127: R33.2@18.669,98.298 R32.2@19.939,98.298 R31.2@21.209,98.298 22.225,99.314 24.257,99.314 24.412,99.469 U3.10@24.412,100.552
AUDIO_RST: R48.2 U5.32 U14.A3 | length 115.2
  TOP w0.102: 29.87,22.847 30.595,22.847 31.213,22.229 32.219,22.229 32.427,22.021 32.427,21.429 v3(32.072,21.074)
  TOP w0.127: v2(9.754,79.629) 9.728,79.604 6.071,79.604 3.683,77.216 3.683,55.956 4.826,54.813 4.826,21.336 6.477,19.685 11.557,19.685 16.383,14.859 25.189,14.859 27.153,16.822 27.153,20.168 28.016,21.031 28.321,21.031 28.956,21.666 28.956,22.276 29.527,22.847 29.87,22.847
  BOTTOM w0.102: v3(32.072,21.074) U14.A3@32.449,21.451
  BOTTOM w0.127: v2(9.754,79.629) 9.754,78.13 9.906,77.978 16.637,77.978 17.399,78.74 17.399,80.01 R48.2@18.161,80.772 17.879,81.054 U5.32@17.879,82.648
BLGND: C55.2 C56.2 C61.2 C63.1 C64.1 C66.1 C79.2 L2.2 R58.1 R59.2 U13.3 U13.9 | length 24.2
  BOTTOM w0.381: U13.9@55.118,40.259 55.443,40.584 U13.3@55.443,41.734
  BOTTOM w0.508: 45.618,46.736 C61.2@46.406,46.736 ; 45.643,49.149 C56.2@46.482,49.149 ; 46.126,52.451 L2.2@46.736,52.451 ; 46.406,45.77 C61.2@46.406,46.736 ; 46.406,47.702 C61.2@46.406,46.736 ; 46.482,48.183 C56.2@46.482,49.149 ; 46.482,50.115 C56.2@46.482,49.149 ; 46.736,51.803 L2.2@46.736,52.451 ; 46.736,53.099 L2.2@46.736,52.451 ; 46.761,51.054 C55.2@47.244,51.054 ; 47.194,46.736 C61.2@46.406,46.736 ; 47.231,44.831 C63.1@47.879,44.831 ; 47.244,50.571 C55.2@47.244,51.054 ; 47.244,51.537 C55.2@47.244,51.054 ; C56.2@47.321,49.149 C56.2@46.482,49.149 ; 47.346,52.451 L2.2@46.736,52.451 ; 47.65,43.434 C64.1@48.133,43.434 ; 47.879,44.221 C63.1@47.879,44.831 ; 47.879,45.441 C63.1@47.879,44.831 ; 48.133,42.951 C64.1@48.133,43.434 ; 48.133,43.917 C64.1@48.133,43.434 ; 53.746,44.958 R59.2@54.356,44.958 ; 54.356,45.555 R59.2@54.356,44.958 ; 54.966,44.958 R59.2@54.356,44.958 ; 55.778,44.958 R58.1@56.388,44.958 ; 56.388,45.555 R58.1@56.388,44.958 ; 56.998,44.958 R58.1@56.388,44.958 ; 57.785,35.966 C66.1@57.785,36.576 ; 57.785,37.186 C66.1@57.785,36.576 ; 58.115,31.419 C79.2@58.115,32.385 ; 58.115,33.351 C79.2@58.115,32.385 ; 58.433,36.576 C66.1@57.785,36.576 ; 58.903,32.385 C79.2@58.115,32.385
  other v2: 47.269,43.028 47.269,43.891 47.015,45.288 53.543,45.466 53.569,46.101 54.229,46.101
BLVDD: C55.1 C56.1 L1.2 L3.1 SB13.2 | length 8.1
  BOTTOM w0.508: 50.292,52.324 50.165,52.451 SB13.2@50.038,52.451 L1.2@48.514,52.451 48.26,52.197 C55.1@48.26,51.054 48.26,50.165 49.276,49.149 50.165,48.26 L3.1@51.308,48.26
BOOT0: R143.1 R150.1 U14.E6 | length 13.3
  TOP w0.102: 34.315,20.472 35.103,21.26 35.103,22.254 34.827,22.53 34.827,23.918 v3(34.472,24.274)
  TOP w0.127: v2(31.75,18.796) 33.147,20.193 34.036,20.193 34.315,20.472
  BOTTOM w0.102: v3(34.472,24.274) U14.E6@34.849,24.651
  BOTTOM w0.127: R150.1@31.115,14.478 30.48,15.113 30.48,17.145 R143.1@31.115,17.78 31.496,18.161 31.496,18.542 v2(31.75,18.796)
CABC: CN10.3 R117.2 | length 13.8
  TOP w0.508: v2(54.102,35.75) 54.61,35.242 54.61,26.924 56.134,25.4 v2(56.134,24.892)
  BOTTOM w0.381: v2(54.102,35.75) 54.102,35.687 R117.2@54.737,35.052 ; CN10.3@55.075,24.717 55.959,24.717 v2(56.134,24.892)
CUR_SEL: U3.22
D0: TP1.1 TP4.1 U11.R8 U14.L12 | length 62
  L4_SIG w0.102: v3(30.963,57.633) 30.556,57.633 30.251,57.328 30.251,55.702 30.124,55.575 29.794,55.575 29.667,55.702 29.667,56.363 29.54,56.49 29.312,56.49 29.185,56.363 29.185,55.448 28.27,54.534 27.203,54.534 26.873,54.204 26.873,53.873 26.746,53.746 26.441,53.746 26.314,53.619 26.314,53.419 26.419,53.315 26.899,53.315 27.026,53.188 27.026,52.476 26.899,52.349 26.086,52.349 25.832,52.095 25.832,50.19 25.273,49.632 25.273,45.466 25.4,45.339 25.984,45.339 26.213,45.11 26.213,44.442 26.332,44.323 27.44,44.323 27.559,44.442 27.559,44.755 27.686,44.882 28.524,44.882 28.651,44.755 28.651,44.425 28.778,44.298 31.914,44.298 32.041,44.171 32.041,40.386 31.914,40.259 31.166,40.259 31.039,40.132 31.039,39.497 31.394,39.141 32.461,39.141 32.588,39.014 v2(32.588,38.823) 32.588,38.557 33.782,37.363 33.782,36.068 33.934,35.916 36.474,35.916 37.073,35.317 37.073,35.174 36.721,34.822 36.721,34.679 36.865,34.534 37.008,34.534 37.36,34.887 37.503,34.887 37.648,34.742 37.648,34.599 37.296,34.247 37.296,34.104 37.44,33.959 37.583,33.959 37.935,34.312 38.078,34.312 38.223,34.167 38.223,34.024 37.871,33.672 37.871,33.529 38.015,33.384 38.158,33.384 38.403,33.63 38.536,33.762 38.704,33.762 38.823,33.643 38.823,33.475 38.446,33.097 38.446,32.953 39.052,32.347 39.256,32.347 39.73,31.873 40.31,31.873 40.437,31.746 40.437,31.191 40.31,31.064 39.98,31.064 39.853,30.937 39.853,30.353 39.98,30.226 40.31,30.226 40.437,30.099 40.437,29.528 40.31,29.401 39.84,29.401 39.501,29.062 v3(39.26,29.062)
  BOTTOM w0.127: TP4.1@26.924,59.69 U11.R8@30.595,58.026 30.963,57.658 v3(30.963,57.633) ; v2(32.588,38.823) 33.02,39.255 TP1.1@33.02,39.878 ; v3(39.26,29.062) U14.L12@39.649,29.451
D1: U11.N7 U14.K13 | length 56.6
  L4_SIG w0.102: v3(31.818,56.849) 31.119,56.849 30.556,56.286 30.556,55.372 30.429,55.245 29.413,55.245 28.397,54.229 27.33,54.229 27.203,54.102 27.203,53.466 27.33,53.34 27.509,53.34 27.635,53.466 27.635,53.848 27.762,53.975 27.94,53.975 28.067,53.848 28.067,52.654 27.457,52.045 26.264,52.045 26.137,51.918 26.137,50.063 25.578,49.505 25.578,45.771 25.705,45.644 26.264,45.644 26.543,45.364 26.543,44.755 26.67,44.628 26.949,44.628 27.076,44.755 27.076,45.06 27.203,45.187 28.829,45.187 28.956,45.06 28.956,44.729 29.083,44.602 32.258,44.602 32.385,44.475 32.385,41.25 32.487,41.149 33.002,41.149 33.122,41.029 33.122,40.861 33.002,40.742 32.511,40.742 32.385,40.616 32.385,40.437 32.511,40.31 32.977,40.31 33.096,40.191 33.096,40.023 32.977,39.904 31.597,39.904 31.471,39.777 31.471,39.598 31.597,39.472 32.995,39.472 33.122,39.345 33.122,38.456 34.088,37.489 34.088,37.236 34.215,37.109 34.493,37.109 34.62,36.982 34.62,36.779 34.493,36.652 34.214,36.652 34.087,36.525 34.087,36.347 34.214,36.22 36.678,36.22 39.311,33.587 39.311,33.443 38.951,33.083 38.951,32.939 39.095,32.795 39.239,32.795 39.599,33.155 39.743,33.155 40.471,32.427 40.471,32.081 40.679,31.873 41.173,31.873 41.3,31.746 41.3,31.166 41.173,31.039 40.691,31.039 40.437,30.785 40.437,30.48 40.665,30.251 41.123,30.251 41.25,30.124 41.25,29.972 41.123,29.845 40.953,29.845 40.826,29.718 v3(40.826,29.028)
  BOTTOM w0.127: v3(31.818,56.849) U11.N7@32.195,57.226 ; U14.K13@40.449,28.651 v3(40.826,29.028)
D2: U11.R9 U14.B12 | length 57.8
  TOP w0.127: v2(31.572,41.783) 32.029,41.783 32.156,41.656 32.156,40.437 32.283,40.31 37.905,40.31 38.032,40.183 38.032,27.144 38.858,26.318 38.858,24.921 38.862,24.917 38.862,24.765 38.989,24.638 39.497,24.638 39.624,24.511 39.624,24.13 39.878,23.876 40.31,23.876 40.437,23.749 40.437,22.53 39.751,21.844 v3(39.243,21.844)
  L4_SIG w0.102: v3(30.988,58.445) 30.977,58.457 30.694,58.457 28.524,56.287 28.524,55.245 28.118,54.839 27.076,54.839 25.883,53.645 25.883,52.578 25.476,52.172 25.476,50.292 24.943,49.759 24.943,44.145 25.07,44.018 25.298,44.018 25.425,44.145 25.425,44.907 25.552,45.034 25.73,45.034 25.857,44.907 25.857,44.12 25.984,43.993 31.445,43.993 31.572,43.866 v2(31.572,41.783)
  BOTTOM w0.127: U11.R9@30.595,58.826 30.608,58.826 v3(30.988,58.445) ; v3@39.243,21.845 U14.B12@39.649,22.251
D3: U11.N8 U14.C12 | length 56.8
  TOP w0.127: v2(31.55,41.123) 31.55,40.03 31.677,39.903 37.49,39.903 37.617,39.776 37.617,32.004 37.236,31.623 37.236,27.203 38.058,26.382 38.058,24.921 38.273,24.706 38.54,24.706 38.862,24.384 38.862,24.003 39.002,23.863 39.472,23.863 39.595,23.74 39.595,23.22 40.026,22.788 v3(40.026,22.674)
  L4_SIG w0.102: v2(31.55,41.123) 31.242,41.123 31.115,41.25 31.115,43.561 30.988,43.688 24.714,43.688 24.587,43.815 24.587,49.86 25.171,50.444 25.171,52.349 25.578,52.756 25.578,53.772 26.975,55.169 27.991,55.169 28.219,55.397 28.219,56.413 30.607,58.801 32.17,58.801 v3(32.53,58.442)
  BOTTOM w0.127: U11.N8@32.195,58.026 32.53,58.361 v3(32.53,58.442) ; U14.C12@39.649,23.051 v3(40.026,22.674)
D4: U11.P9 U14.R8 | length 60
  L4_SIG w0.102: v3(31.876,58.422) 32.206,58.092 32.206,55.624 31.451,54.87 31.451,54.514 30.582,53.645 30.582,52.502 30.937,52.146 30.937,50.927 30.81,50.8 27.508,50.8 27.381,50.673 27.381,49.987 27.661,49.708 27.661,47.447 27.788,47.32 28.931,47.32 29.058,47.193 29.058,46.99 29.185,46.863 32.436,46.863 34.023,45.276 34.519,45.276 34.646,45.149 34.646,40.996 v2(34.722,40.919)
  BOTTOM w0.127: U11.P9@31.395,58.826 31.471,58.826 v3(31.876,58.422) ; v2(34.722,40.919) 34.722,41.91 34.595,42.037 34.214,42.037 34.087,41.91 34.087,38.811 34.214,38.684 34.544,38.684 34.671,38.557 34.671,38.329 34.544,38.202 30.759,38.202 30.632,38.075 30.632,37.846 30.759,37.719 34.468,37.719 34.595,37.592 34.595,35.281 34.468,35.154 28.753,35.154 28.626,35.027 28.626,34.671 28.753,34.544 34.556,34.544 U14.R8@36.449,32.651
